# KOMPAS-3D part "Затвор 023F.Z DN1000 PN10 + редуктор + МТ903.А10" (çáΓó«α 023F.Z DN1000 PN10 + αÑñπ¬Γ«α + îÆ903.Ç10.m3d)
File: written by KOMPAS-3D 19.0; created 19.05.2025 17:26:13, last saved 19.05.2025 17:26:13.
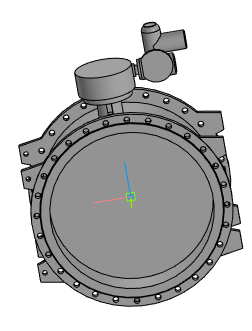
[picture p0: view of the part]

Document properties: Полное имя файла: Затвор 023F.Z DN1000 PN10 + редуктор + МТ903.А10.a3d

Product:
- Part/product: Затвор 023F.Z DN1000 PN10 + редуктор + МТ903.А10
    Масса: 1391.25

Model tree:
1. Операция без истории:1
